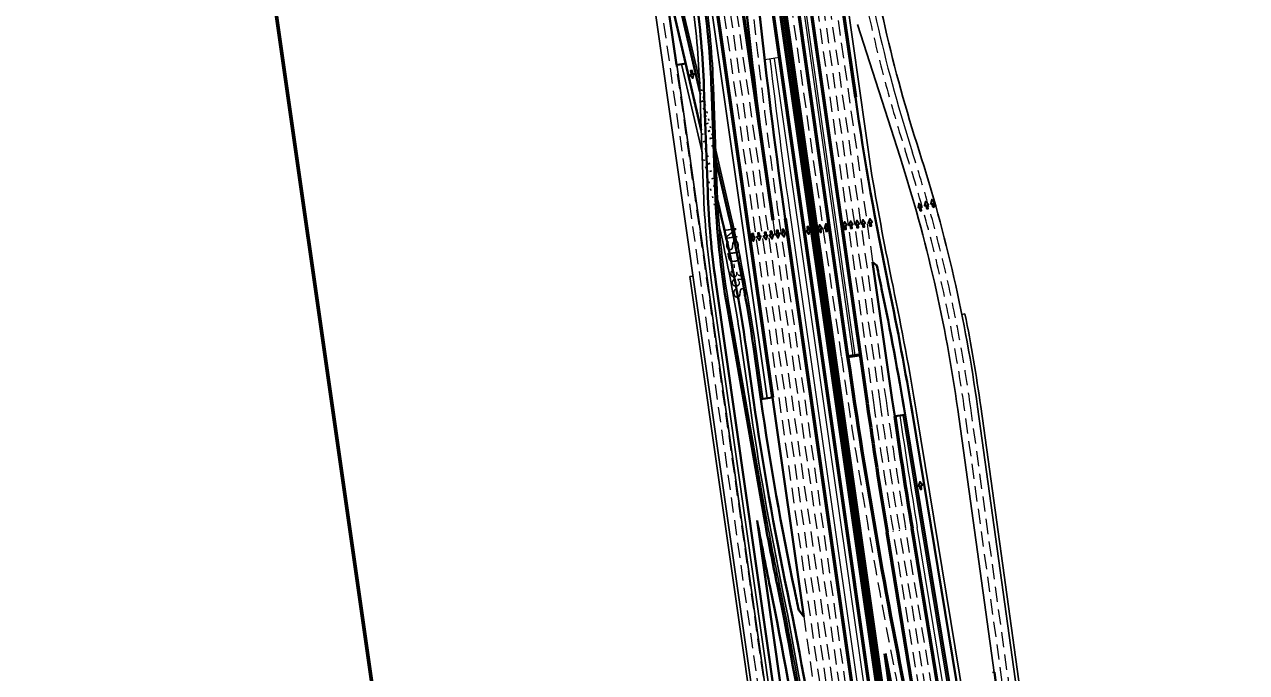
# Model space of a CAD drawing. Extents: x 2329387 to 2347382, y 6951580 to 6987999.
# Drawn here: x 2329937 to 2332250, y 6968230 to 6969457 of the extents above; entities that cross this region are included whole.
import ezdxf

# ---------------------------------------------------------------- set-up
doc = ezdxf.new("R2010")
doc.units = 0
doc.header["$LTSCALE"] = 9.6
doc.linetypes.add('DOTTED', pattern=[1.5, 0.3, -1.2])
doc.linetypes.add('MEDIUM_DASHED', pattern=[4.5, 3, -1.5])
for name, color, linetype, lineweight in [('26', 7, 'Continuous', 53), ('27', 7, 'Continuous', 40), ('28', 7, 'Continuous', 25), ('30', 7, 'Continuous', 13), ('31', 7, 'Continuous', 53), ('41', 7, 'Continuous', 35), ('50', 7, 'MEDIUM_DASHED', 13), ('62', 7, 'Continuous', 60)]:
    doc.layers.add(name, color=color, linetype=linetype, lineweight=lineweight)
doc.layers.add('40', color=7, linetype='Continuous')

msp = doc.modelspace()

# ---------------------------------------------------------------- linework, layer by layer
at = {"layer": '26', "lineweight": 13}
for p, q in [((2331194.647, 6971027.301), (2331508.441, 6968830.155)), ((2331386.358, 6969090.842), (2331675.68, 6967065.044)), ((2331752.956, 6967735.909), (2331626.312, 6968504.454))]:
    msp.add_line(p, q, dxfattribs=at)
at = {"layer": '26'}
for p, q in [((2331204.547, 6971028.714), (2331531.518, 6968739.307)), ((2331305.118, 6970748.901), (2331509.335, 6969318.999)), ((2331173.611, 6970000.486), (2331352.172, 6968750.231)), ((2331376.458, 6969089.428), (2331665.791, 6967063.557)), ((2331743.089, 6967734.283), (2331616.446, 6968502.828))]:
    msp.add_line(p, q, dxfattribs=at)
at = {"layer": '26', "lineweight": 25}
for p, q in [((2331299.907, 6970856.121), (2331540.622, 6969170.663)), ((2331163.712, 6969999.072), (2331342.272, 6968748.817))]:
    msp.add_line(p, q, dxfattribs=at)
at = {"layer": '26'}
msp.add_arc((2342934.961, 6970367.934), 11471.156, 188.28645, 189.35731, dxfattribs=at)
at = {"layer": '26', "lineweight": 13}
msp.add_arc((2342934.961, 6970367.934), 11461.156, 188.28645, 189.35731, dxfattribs=at)
at = {"layer": '27'}
for p, q in [((2331170.338, 6969380.127), (2331139.96, 6969593.801)), ((2331217.589, 6969256.243), (2331150.298, 6969545.603)), ((2331214.872, 6969329.735), (2331163.934, 6969548.774)), ((2331172.318, 6969380.409), (2331188.189, 6969382.665)), ((2331222.674, 6969337.451), (2331229.768, 6969140.175)), ((2331236.665, 6969337.954), (2331243.759, 6969140.678)), ((2331270.35, 6969091.17), (2331245.63, 6969197.47)), ((2331256.714, 6969087.999), (2331248.96, 6969121.344)), ((2331541.861, 6969006.386), (2331549.828, 6969000.112)), ((2331541.861, 6969006.386), (2331579.03, 6968746.131)), ((2331411.649, 6967796.46), (2331245.008, 6968968.587)), ((2331266.998, 6968919.276), (2331328.799, 6968566.069)), ((2331302.394, 6968844.139), (2331316.533, 6968745.141)), ((2331316.254, 6968846.119), (2331330.393, 6968747.121)), ((2331352.172, 6968750.231), (2331330.392, 6968747.123)), ((2331352.119, 6968750.602), (2331411.345, 6968335.905)), ((2331603.357, 6968717.568), (2331583.565, 6968714.686)), ((2331767.682, 6967720.351), (2331603.357, 6968717.568)), ((2331721.486, 6968086.798), (2331617.17, 6968719.844)), ((2331411.345, 6968335.905), (2331401.884, 6968347.412))]:
    msp.add_line(p, q, dxfattribs=at)
at = {"layer": '27', "lineweight": 25}
for p, q in [((2331214.085, 6969350.778), (2331167.83, 6969549.68)), ((2331219.091, 6969214.464), (2331180.239, 6969381.535)), ((2331214.679, 6969337.164), (2331216.801, 6969278.156)), ((2331240.662, 6969338.098), (2331247.756, 6969140.822)), ((2331274.246, 6969092.076), (2331244.811, 6969218.654)), ((2331403.729, 6967795.334), (2331237.088, 6968967.461)), ((2331270.938, 6968919.965), (2331332.739, 6968566.758)), ((2331294.475, 6968843.008), (2331308.614, 6968744.01)), ((2331320.214, 6968846.683), (2331334.352, 6968747.686)), ((2331729.38, 6968088.098), (2331625.064, 6968721.145)), ((2331763.735, 6967719.701), (2331599.398, 6968716.991)), ((2331772.597, 6968230.077), (2331768.635, 6968229.529))]:
    msp.add_line(p, q, dxfattribs=at)
at = {"layer": '27', "linetype": 'DOTTED', "lineweight": 25}
for p, q in [((2331244.811, 6969218.654), (2331214.085, 6969350.778)), ((2331248.922, 6969086.187), (2331219.091, 6969214.464))]:
    msp.add_line(p, q, dxfattribs=at)
at = {"layer": '27', "linetype": 'DOTTED'}
for p, q in [((2331245.63, 6969197.47), (2331214.872, 6969329.735)), ((2331248.96, 6969121.344), (2331217.589, 6969256.243))]:
    msp.add_line(p, q, dxfattribs=at)
at = {"layer": '27', "lineweight": 25}
msp.add_lwpolyline([(2331216.801, 6969278.156), (2331218.758, 6969223.742), (2331221.773, 6969139.887)], dxfattribs=at)
at = {"layer": '27'}
msp.add_lwpolyline([(2331425.511, 6967798.421), (2331383.284, 6968095.444), (2331323.287, 6968517.451)], dxfattribs=at)
at = {"layer": '27', "lineweight": 25}
for centre, radius, start, end in [((2329586.709, 6969278.62), 1629.022, 2.05953, 8.12795), ((2329586.709, 6969278.62), 1655.022, 2.05953, 8.12795), ((2329623.637, 6969281.912), 1592, 2.05953, 2.74825), ((2337181.359, 6970129.071), 5721.578, 189.64293, 191.78698), ((2332865.733, 6969199.006), 1645.022, 182.05953, 188.09153), ((2332865.733, 6969199.006), 1619.022, 182.05953, 189.92456), ((2328466.383, 6968439.103), 2882.789, 8.12795, 13.09153), ((2328466.383, 6968439.103), 2856.789, 8.12795, 12.70707), ((2325963.833, 6967788.267), 5737.578, 9.35731, 11.78698), ((2336988.397, 6969556.327), 5737.578, 188.1392, 191.83684), ((2336988.397, 6969556.327), 5741.578, 189.92456, 191.67456), ((2325738.879, 6967231.872), 5745.578, 8.12795, 11.67456), ((2325758.591, 6967235.313), 5729.578, 8.12795, 11.51824)]:
    msp.add_arc(centre, radius, start, end, dxfattribs=at)
at = {"layer": '27'}
for centre, radius, start, end in [((2329586.709, 6969278.62), 1637.022, 2.05953, 8.12795), ((2329586.709, 6969278.62), 1651.022, 2.6386, 8.12795), ((2329586.709, 6969278.62), 1651.022, 2.05953, 2.63802), ((2337181.359, 6970129.071), 5729.578, 188.12795, 191.78698), ((2332865.733, 6969199.006), 1637.022, 182.05953, 188.09153), ((2332865.733, 6969199.006), 1623.022, 182.05953, 189.92456), ((2328466.383, 6968439.103), 2878.789, 8.12795, 13.09153), ((2328466.383, 6968439.103), 2864.789, 8.12795, 13.09153), ((2337181.359, 6970129.071), 5743.578, 191.33588, 191.78698), ((2325963.833, 6967788.267), 5715.578, 9.35731, 11.78698), ((2325963.833, 6967788.267), 5729.578, 9.35731, 11.78698), ((2336988.397, 6969556.327), 5729.578, 188.1392, 191.83684), ((2336988.397, 6969556.327), 5715.578, 188.1392, 191.83684), ((2342934.961, 6970367.934), 11471.156, 188.12776, 188.28645), ((2336988.397, 6969556.327), 5745.578, 189.92456, 191.67456), ((2336988.397, 6969556.327), 5759.578, 190.39152, 191.67456), ((2325738.879, 6967231.872), 5727.578, 8.12795, 11.67456), ((2325738.879, 6967231.872), 5741.578, 8.12795, 11.67456), ((2325772.912, 6967205.762), 5729.578, 8.12795, 11.83684), ((2325772.912, 6967205.762), 5743.578, 11.46503, 11.83684), ((2328948.693, 6967839.484), 2850.789, 2.87499, 7.87499)]:
    msp.add_arc(centre, radius, start, end, dxfattribs=at)
at = {"layer": '27', "linetype": 'DOTTED', "lineweight": 25}
msp.add_arc((2328466.383, 6968439.103), 2856.789, 12.70707, 13.09153, dxfattribs=at)
at = {"layer": '28'}
for p, q in [((2331390.789, 6967651.904), (2331040.416, 6970116.36)), ((2331512.931, 6969456.595), (2331593.697, 6969205.601)), ((2331396.799, 6967794.349), (2331171.328, 6969380.268)), ((2331201.967, 6968980.043), (2331196.027, 6968979.198)), ((2331710.729, 6968907.361), (2331716.611, 6968908.549)), ((2331771.606, 6968229.94), (2331702.812, 6968727.309)), ((2332078.029, 6966291.919), (2331740.454, 6968732.516)), ((2331881.451, 6967756.928), (2331746.397, 6968733.338))]:
    msp.add_line(p, q, dxfattribs=at)
msp.add_lwpolyline([(2331342.848, 6967989.112), (2331336.908, 6967988.268), (2331196.027, 6968979.198)], dxfattribs=at)
for centre, radius, start, end in [((2334356.15, 6970093.989), 2863.789, 188.12795, 197.82748), ((2328901.691, 6968339.868), 2865.789, 7.87499, 17.82748), ((2328901.691, 6968339.868), 2827.789, 7.87499, 17.82748), ((2328901.691, 6968339.868), 2871.789, 7.87499, 11.4214)]:
    msp.add_arc(centre, radius, start, end, dxfattribs=at)
at = {"layer": '30', "lineweight": 53}
for p, q in [((2330745.804, 6973901.275), (2331470.823, 6968824.782)), ((2331004.304, 6972261.043), (2331494.582, 6968828.175)), ((2331238.034, 6969888.911), (2331352.7, 6969086.035)), ((2331494.582, 6968828.175), (2331516.361, 6968831.286)), ((2331695.724, 6967726.499), (2331569.084, 6968495.023))]:
    msp.add_line(p, q, dxfattribs=at)
at = {"layer": '30'}
for p, q in [((2330741.844, 6973900.709), (2331466.866, 6968824.195)), ((2331014.231, 6972262.259), (2331504.482, 6968829.589))]:
    msp.add_line(p, q, dxfattribs=at)
at = {"layer": '30', "lineweight": 40}
for radius in [11500, 11476]:
    msp.add_arc((2342737.18, 6970711.953), radius, 184.50364, 188.12795, dxfattribs=at)
at = {"layer": '30'}
msp.add_arc((2342737.18, 6970711.953), 11466, 186.61448, 188.12795, dxfattribs=at)
at = {"layer": '30', "lineweight": 53}
for centre, radius, start, end in [((2342838.628, 6970448.32), 11459.156, 188.12796, 191.75872), ((2342934.961, 6970367.934), 11519.156, 188.12795, 189.35731), ((2342838.628, 6970448.32), 11483.156, 190.95749, 191.75872)]:
    msp.add_arc(centre, radius, start, end, dxfattribs=at)
at = {"layer": '31'}
for p, q in [((2331296.241, 6969976.458), (2331690.26, 6967217.584)), ((2331333.019, 6969619.916), (2331676.4, 6967215.605)), ((2331470.826, 6968824.761), (2331700.159, 6967218.998)), ((2331564.828, 6968265.595), (2331714.019, 6967220.977))]:
    msp.add_line(p, q, dxfattribs=at)
at = {"layer": '31', "lineweight": 13}
for p, q in [((2331300.2, 6969977.023), (2331694.22, 6967218.149)), ((2331365.32, 6969393.75), (2331337.598, 6969389.791)), ((2331355.421, 6969392.336), (2331666.501, 6967214.191)), ((2331466.866, 6968824.195), (2331696.2, 6967218.432))]:
    msp.add_line(p, q, dxfattribs=at)
at = {"layer": '41'}
for points in [[(2331200.17, 6969369.147), (2331197.245, 6969368.474), (2331198.771, 6969361.841), (2331196.396, 6969361.294), (2331201.693, 6969355.125), (2331203.761, 6969362.989), (2331201.696, 6969362.513)], [(2331631.564, 6969103.835), (2331634.458, 6969104.63), (2331632.655, 6969111.194), (2331635.005, 6969111.839), (2331629.454, 6969117.781), (2331627.718, 6969109.837), (2331629.762, 6969110.399)], [(2331631.564, 6969103.835), (2331634.458, 6969104.63), (2331632.655, 6969111.194), (2331635.005, 6969111.839), (2331629.454, 6969117.781), (2331627.718, 6969109.837), (2331629.762, 6969110.399)], [(2331644.176, 6969107.494), (2331647.07, 6969108.289), (2331645.267, 6969114.852), (2331647.617, 6969115.498), (2331642.066, 6969121.44), (2331640.329, 6969113.496), (2331642.373, 6969114.058)], [(2331644.176, 6969107.494), (2331647.07, 6969108.289), (2331645.267, 6969114.852), (2331647.617, 6969115.498), (2331642.066, 6969121.44), (2331640.329, 6969113.496), (2331642.373, 6969114.058)], [(2331655.912, 6969110.899), (2331658.805, 6969111.694), (2331657.002, 6969118.257), (2331659.353, 6969118.903), (2331653.802, 6969124.845), (2331652.065, 6969116.901), (2331654.109, 6969117.462)], [(2331655.912, 6969110.899), (2331658.805, 6969111.694), (2331657.002, 6969118.257), (2331659.353, 6969118.903), (2331653.802, 6969124.845), (2331652.065, 6969116.901), (2331654.109, 6969117.462)], [(2331374.004, 6969068.55), (2331371.032, 6969068.137), (2331371.969, 6969061.395), (2331369.554, 6969061.059), (2331374.288, 6969054.448), (2331377.04, 6969062.099), (2331374.941, 6969061.808)], [(2331420.905, 6969073.545), (2331417.932, 6969073.132), (2331418.869, 6969066.39), (2331416.455, 6969066.055), (2331421.188, 6969059.443), (2331423.941, 6969067.095), (2331421.841, 6969066.803)], [(2331441.75, 6969063.044), (2331444.722, 6969063.457), (2331443.786, 6969070.199), (2331446.2, 6969070.534), (2331441.466, 6969077.146), (2331438.714, 6969069.494), (2331440.814, 6969069.786)], [(2331453.54, 6969064.715), (2331456.512, 6969065.128), (2331455.576, 6969071.87), (2331457.99, 6969072.205), (2331453.256, 6969078.817), (2331450.504, 6969071.165), (2331452.603, 6969071.457)], [(2331488.783, 6969068.838), (2331491.756, 6969069.249), (2331490.822, 6969075.991), (2331493.237, 6969076.325), (2331488.507, 6969082.94), (2331485.75, 6969075.289), (2331487.85, 6969075.58)], [(2331499.973, 6969070.334), (2331502.946, 6969070.745), (2331502.013, 6969077.488), (2331504.427, 6969077.822), (2331499.697, 6969084.436), (2331496.941, 6969076.786), (2331499.04, 6969077.077)], [(2331512.127, 6969071.419), (2331515.099, 6969071.83), (2331514.166, 6969078.573), (2331516.581, 6969078.907), (2331511.85, 6969085.521), (2331509.094, 6969077.871), (2331511.194, 6969078.161)], [(2331523.438, 6969072.744), (2331526.411, 6969073.156), (2331525.478, 6969079.898), (2331527.892, 6969080.232), (2331523.162, 6969086.846), (2331520.406, 6969079.196), (2331522.505, 6969079.487)], [(2331536.529, 6969074.614), (2331539.501, 6969075.025), (2331538.568, 6969081.768), (2331540.982, 6969082.102), (2331536.252, 6969088.716), (2331533.496, 6969081.066), (2331535.596, 6969081.356)], [(2331316.165, 6969060.475), (2331313.193, 6969060.063), (2331314.13, 6969053.321), (2331311.716, 6969052.985), (2331316.449, 6969046.373), (2331319.201, 6969054.025), (2331317.102, 6969053.733)], [(2331327.288, 6969062.095), (2331324.316, 6969061.682), (2331325.253, 6969054.94), (2331322.839, 6969054.605), (2331327.572, 6969047.993), (2331330.324, 6969055.645), (2331328.225, 6969055.353)], [(2331340.05, 6969063.337), (2331337.078, 6969062.924), (2331338.015, 6969056.182), (2331335.601, 6969055.847), (2331340.334, 6969049.235), (2331343.086, 6969056.887), (2331340.987, 6969056.595)], [(2331351.173, 6969064.957), (2331348.201, 6969064.544), (2331349.138, 6969057.802), (2331346.724, 6969057.467), (2331351.457, 6969050.855), (2331354.209, 6969058.507), (2331352.11, 6969058.215)], [(2331362.881, 6969066.93), (2331359.909, 6969066.517), (2331360.846, 6969059.775), (2331358.431, 6969059.44), (2331363.165, 6969052.828), (2331365.917, 6969060.479), (2331363.818, 6969060.188)], [(2331631.525, 6968576.576), (2331634.498, 6968576.988), (2331633.565, 6968583.73), (2331635.979, 6968584.064), (2331631.249, 6968590.678), (2331628.493, 6968583.028), (2331630.592, 6968583.319)]]:
    msp.add_lwpolyline(points, close=True, dxfattribs=at)
at = {"layer": '50'}
for p, q in [((2330757.684, 6973902.971), (2331482.703, 6968826.479)), ((2330631.386, 6973881.958), (2331606.386, 6967055.128)), ((2330643.265, 6973883.655), (2331618.272, 6967056.781)), ((2330655.145, 6973885.352), (2331630.147, 6967058.504)), ((2331240.185, 6971033.804), (2331567.156, 6968744.397)), ((2331216.426, 6971030.411), (2331543.397, 6968741.003)), ((2331228.306, 6971032.108), (2331555.277, 6968742.7)), ((2331637.49, 6966009.015), (2330956.52, 6970798.829)), ((2331293.239, 6970747.205), (2331541.861, 6969006.386)), ((2331395.809, 6967794.208), (2331170.338, 6969380.127)), ((2331352.7, 6969086.035), (2331642.032, 6967060.168)), ((2331364.579, 6969087.731), (2331653.902, 6967061.926)), ((2331799.148, 6968125.702), (2331715.689, 6968729.091)), ((2332198.633, 6965325.094), (2331727.576, 6968730.735)), ((2331707.565, 6967728.45), (2331580.925, 6968496.975)), ((2331719.405, 6967730.401), (2331592.765, 6968498.926)), ((2331731.245, 6967732.353), (2331604.605, 6968500.877)), ((2331411.345, 6968335.905), (2331555.784, 6967324.562))]:
    msp.add_line(p, q, dxfattribs=at)
for centre, radius, start, end in [((2342737.18, 6970711.953), 11488, 184.50364, 188.12795), ((2334356.15, 6970093.989), 2888.789, 188.12795, 197.82748), ((2328901.691, 6968339.868), 2840.789, 7.87499, 17.82748), ((2328901.691, 6968339.868), 2852.789, 7.87499, 17.82748), ((2342838.628, 6970448.32), 11471.156, 188.12796, 191.75872), ((2342934.961, 6970367.934), 11483.156, 188.12795, 189.35731), ((2342934.961, 6970367.934), 11507.156, 188.12795, 189.35731), ((2342934.961, 6970367.934), 11495.156, 188.12795, 189.35731)]:
    msp.add_arc(centre, radius, start, end, dxfattribs=at)
at = {"layer": '50', "linetype": 'Continuous'}
msp.add_arc((2334356.15, 6970093.989), 2876.789, 188.12795, 197.82748, dxfattribs=at)
at = {"layer": '62'}
msp.add_lwpolyline([(2329936.564, 6972812.843), (2331011.084, 6965289.186), (2332891.999, 6965557.816), (2331817.479, 6973081.473)], close=True, dxfattribs=at)

# ---------------------------------------------------------------- texts
at = {"layer": '40'}
msp.add_text('NSD-35S', height=24, rotation=278.89, dxfattribs=at).set_placement((2331259.364, 6969070.297))

doc.saveas('drawing.dxf')
